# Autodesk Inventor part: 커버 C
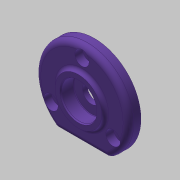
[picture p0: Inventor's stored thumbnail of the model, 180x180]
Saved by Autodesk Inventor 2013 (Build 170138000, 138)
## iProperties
Created: 2020-04
Part Number: 커버 C
Material: 알루미늄 6061
Document SubType Name: Modeling
Designer: mduedu
Density: 1 g/cm^3
Author: mduedu
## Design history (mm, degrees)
sketch "스케치1"
  geometry: C1 r 26 at (0, 0); 1 further point
  constraints: 1 centre point, 1 coincident
  dimensions: "d0" = 52 diameter of C1
extrude "돌출1" new body sketch "스케치1" distance "d1" = 7; taper "d2" = 0 deg
sketch "스케치2"
  geometry: L1 (-14.62, -21.5)-(14.62, -21.5); A1 r 26 centre (0, 0) between (-14.62, -21.5) and (14.62, -21.5) reference; 1 further point
  constraints: 2 end point, 2 point on circle, 1 horizontal
  dimensions: "d3" = 21.5 distance from line of L1 point (0, 0)
extrude "돌출2" cut sketch "스케치2" stored distance "d4" = 7; taper "d5" = 0 deg
sketch "스케치6"
  geometry: C1 r 13 at (0, 0); 1 further point
  constraints: 1 centre point, 1 coincident
  dimensions: "d29" = 26 diameter of C1
extrude "돌출5" join sketch "스케치6" distance "d30" = 2; taper "d31" = 0 deg
fillet "모깎기1" dims "d6" = 3
fillet "모깎기2" dims "d7" = 3
fillet "모깎기4" dims "d33" = 2
sketch "스케치3" dims "d8" = 40
  geometry: 3 further points
  constraints: 2 vertical alignment, 1 coincident, 2 other
hole "구멍1" sketch "스케치3" at (0, 20) diameter "d9" = 4.5; stored, may be unused: countersink angle "d13" = 90 deg, drill point angle "d15" = 118 deg; dims "d10" = 6, "d11" = 8, "d12" = 4.4, "d14" = 8
sketch "스케치4"
  geometry: C1 r 14 at (0, 0); 1 further point
  constraints: 1 centre point, 1 coincident
  dimensions: "d19" = 28 diameter of C1
extrude "돌출3" join sketch "스케치4" distance "d20" = 4; taper "d21" = 0 deg
sketch "스케치5"
  geometry: C1 r 12 at (0, 0); 1 further point
  constraints: 1 centre point, 1 coincident
  dimensions: "d22" = 24 diameter of C1
extrude "돌출4" cut sketch "스케치5" distance "d23" = 3; taper "d24" = 0 deg
fillet "모깎기3" dims "d25" = 3
chamfer "모따기1" distance "d26" = 0.5; stored, may be unused: second distance "d27" = 2, angle "d28" = 45 deg
sketch "스케치7"
  geometry: 2 further points
  constraints: 1 coincident
hole "구멍2" sketch "스케치7" at (0, 0) diameter "d34" = 10; stored, may be unused: countersink angle "d38" = 90 deg, drill point angle "d40" = 118 deg; dims "d35" = 6, "d36" = 20, "d37" = 7.3, "d39" = 8
fillet "모깎기5" dims "d41" = 0.3
chamfer "모따기2" distance "d42" = 0.7; stored, may be unused: second distance "d43" = 2, angle "d44" = 30 deg
node "솔리드1"
pattern_circular "원형 패턴1" dims angle "d17" = 360 deg
node "투영된 루프1"
